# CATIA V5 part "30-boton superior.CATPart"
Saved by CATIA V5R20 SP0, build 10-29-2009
Part number: 30-boton superior
Revision: ANY
Definition: UNKNOWN
Nomenclature: 30-boton superior
Source: Unknown
Bounding box of the stored display mesh (mm): x -2.725 to 10.054, y 0 to 6.1, z -10.054 to 2.75
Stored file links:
  C:\Users\Utente\Desktop\IO LAVORO\3D X SITO CF\CUMSA\3D files CC\CCHS5328\30-boton superior.CATPart
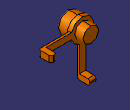
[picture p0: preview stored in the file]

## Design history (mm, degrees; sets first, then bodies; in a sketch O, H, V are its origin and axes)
Body1 "Redondeo1" (main body)
  Solid1: solid without history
